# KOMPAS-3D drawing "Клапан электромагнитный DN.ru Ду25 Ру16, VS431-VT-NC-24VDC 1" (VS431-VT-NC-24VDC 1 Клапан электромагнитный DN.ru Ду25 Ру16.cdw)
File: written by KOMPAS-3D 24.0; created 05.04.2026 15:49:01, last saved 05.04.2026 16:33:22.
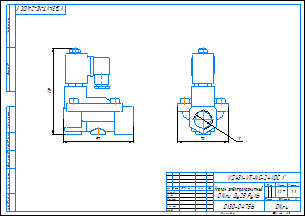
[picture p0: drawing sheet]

Document properties: c3d_UniqueCompID: ef56311e-7521-43dc-8291-0e6108b3d81d; Автор: artio; Класс точности: c; Знак неуказанной шероховатости: Шероховатость не задана; Рассекать на разрезах: Да; c3d_UniqueCompID: ef56311e-7521-43dc-8291-0e6108b3d81d; Автор: artio; Класс точности: c; Знак неуказанной шероховатости: Шероховатость не задана; Рассекать на разрезах: Да; Автор: artio; Форматы листов документа: A3; Полное имя файла: VS431-VT-NC-24VDC 1 Клапан электромагнитный DN.ru Ду25 Ру16.m3d; Масса: 1.267; Наименование: Клапан электромагнитный DN.ru Ду25 Ру16; Количество листов документа: 1; Примечание: D130-04756

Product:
- Body: Тело 1  | qty 1
    Масса: 1.729172
- Part/product: Клапан электромагнитный DN.ru Ду25 Ру16  | designation VS431-VT-NC-24VDC 1
    Масса: 1.267
    Раздел спецификации: Прочие изделия
    Примечание: D130-04756
    additional columns: ef56311e-7521-43dc-8291-0e6108b3d81d; artio; c; Шероховатость не задана; Да

Views: Вид 1, Спереди, Проекционный вид 2
Referenced files in C:\Users\artio\OneDrive\Рабочий стол\Клапан электромагнитный DN.ru\VS431\VS431-ET-NC\: VS431-ET-NC-24VDC 3-4 Клапан электромагнитный DN.ru Ду20 Ру16.m3d, VS431-ET-NC-24VDC 3-4 Клапан электромагнитный DN.ru Ду20 Ру16.cdw
Referenced files in C:\Users\artio\OneDrive\Рабочий стол\Клапан электромагнитный DN.ru\VS431\VS431-VT-NC\: VS431-VT-NC-24VDC 1 Клапан электромагнитный DN.ru Ду25 Ру16.m3d
Referenced files in C:\Users\artio\OneDrive\Рабочий стол\Клапан электромагнитный DN.ru\VS431\VS431-VT-NC\VS431-VT-NC-24VDC\Ду25\: VS431-VT-NC-24VDC 1 Клапан электромагнитный DN.ru Ду25 Ру16.m3d
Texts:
  VS431-VT-NC-24VDC 1
  Клапан электромагнитный
  DN.ru Ду25 Ру16
  VS431-VT-NC-24VDC 1"
  VS431-VT-NC-24VDC 1"-
  Клапан электромагнитный DN.ru Ду25 Ру16
  VS431-VT-NC-24VDC 1 Клапан электромагнитный DN.ru Ду25 Ру16
Dimensions and other numbers on the sheet: 0; 3; 2; 4; 70; 97; 119; 1:1; 1; 1,27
